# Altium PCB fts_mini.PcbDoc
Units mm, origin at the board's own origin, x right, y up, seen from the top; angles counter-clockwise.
Board outline 46.2 x 15 mm, 2 copper layers (Top Layer, Bottom Layer); 15 components, 14 nets, 42 pads, 0 vias.
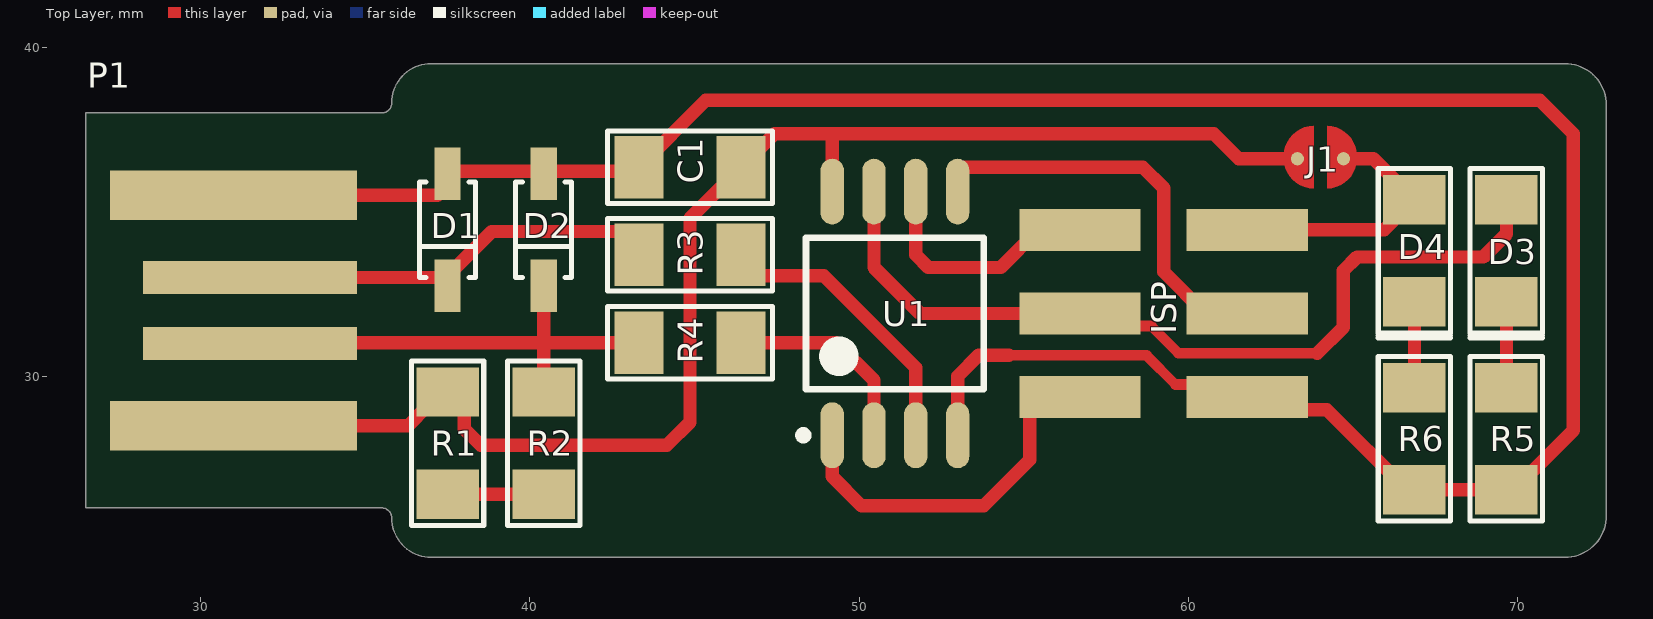
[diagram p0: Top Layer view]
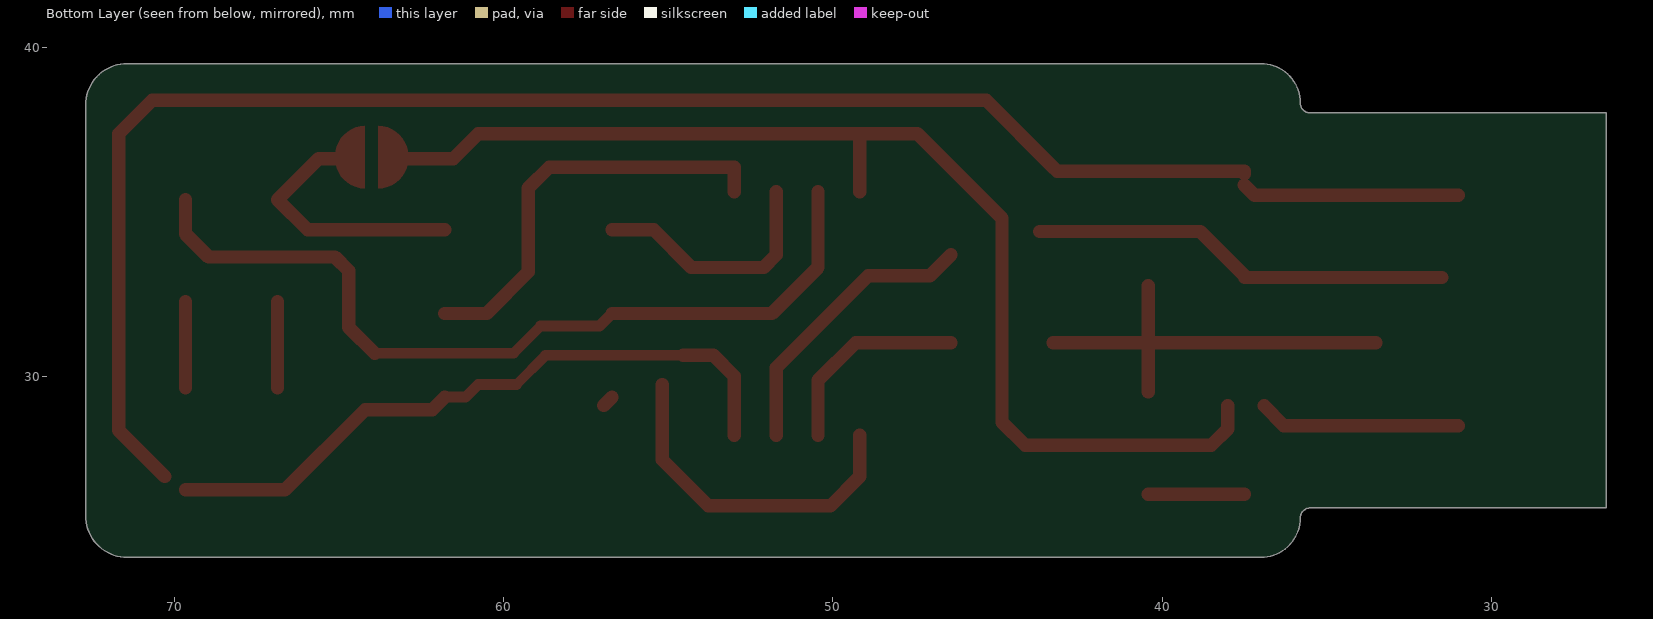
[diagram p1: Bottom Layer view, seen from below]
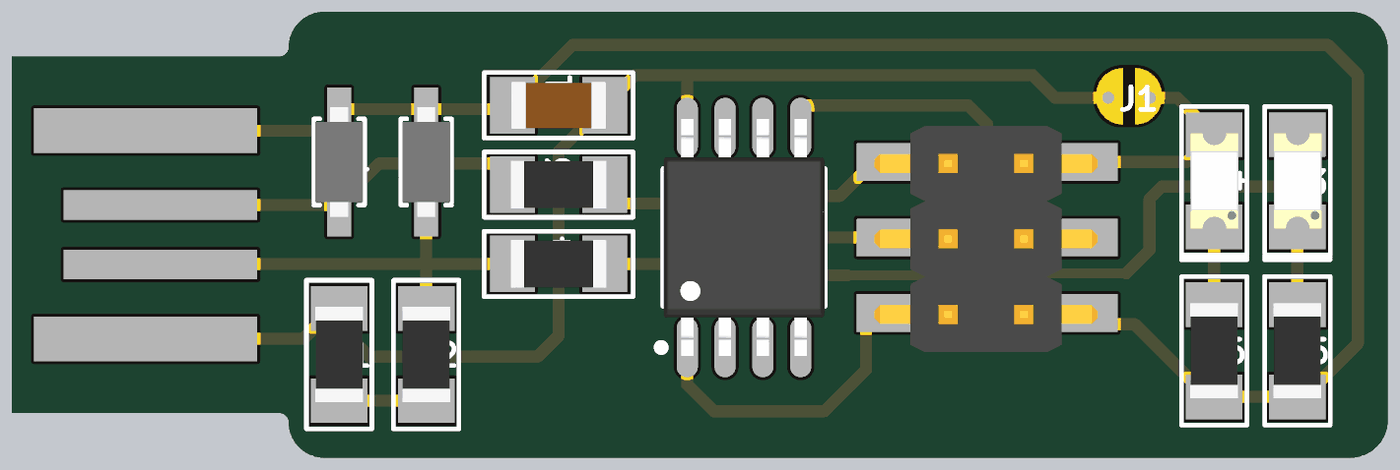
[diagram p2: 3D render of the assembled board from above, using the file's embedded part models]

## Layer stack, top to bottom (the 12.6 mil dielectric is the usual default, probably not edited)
Top Solder: solder mask 0.0102, Solder Resist, Dk 3.5
Top Layer: signal copper 0.0356
Dielectric 1: dielectric 0.32, FR-4, Dk 4.8
Bottom Layer: signal copper 0.0356
Bottom Solder: solder mask 0.0102, Solder Resist, Dk 3.5

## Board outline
26.5,26 26.5,38 35.5,38 ccw(c35.5,38.3) 35.8,38.3 cw(c37,38.3) 37,39.5 71.43,39.5 cw(c71.43,38.23) 72.7,38.23 72.7,25.77 cw(c71.43,25.77) 71.43,24.5 37,24.5 cw(c37,25.7) 35.8,25.7 ccw(c35.5,25.7) 35.5,26

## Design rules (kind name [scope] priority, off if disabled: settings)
Clearance [All] p1: gap=0.406
MinimumSolderMaskSliver [All] p1: minsoldermaskwidth=0
MinimumSolderMaskSliver SilkscreenOverComponentPads [All] p2: minsoldermaskwidth=0.254
PolygonConnect [All] p1: connectstyle=Relief reliefconductorwidth=0.254 reliefentries=4 polygonreliefangle="90 Angle" airgapwidth=0.254
RoutingVias [All] p1: holewidth=0.711 width=1.27 viastyle="Through Hole" minholewidth=0.711 minwidth=1.27 maxholewidth=0.711 maxwidth=1.27
SilkToSilkClearance [All] p1: silktosilkclearance=0
SolderMaskExpansion [All] p1: expansion=0.102
Width [All] p1: maxlimit=2.54 minlimit=0.152 preferedwidth=0.203
28 further rules are at their usual default settings.

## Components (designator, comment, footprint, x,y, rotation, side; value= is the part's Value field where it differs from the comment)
C1 "100nF" 1206C 44.862,36.353 r0 top
D1 "3.3V" SOD123 37.496,34.448 r270 top
D2 "3.3V" SOD123 40.417,34.448 r270 top
D3 "LED GREEN" 1206LED 69.662,33.813 r270 top
D4 "LED RED" 1206LED 66.868,33.813 r270 top
ISP "Header 3X2" 100MIL_SMT_ISP_HEADER 56.708,31.908 r0 top
J1 "Solder Jumper" JMP_1.9mm 64.212,37.607 r180 top
P1 "USB_A" USB_PCB 31,32 r270 top
R1 "1k" 1206R 37.496,27.971 r270 top
R2 "499" 1206R 40.417,27.971 r270 top
R3 "49" 1206R 44.862,33.686 r180 top
R4 "49" 1206R 44.862,31.019 r180 top
R5 "499" 1206R 69.662,28.098 r270 top
R6 "1k" 1206R 66.868,28.098 r270 top
U1 "ATtiny45" SOIC8_WIDE 51.085,31.908 r90 top

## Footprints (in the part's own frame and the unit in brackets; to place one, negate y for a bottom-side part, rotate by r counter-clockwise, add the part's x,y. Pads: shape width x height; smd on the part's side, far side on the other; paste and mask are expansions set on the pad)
100MIL_SMT_ISP_HEADER [mil]
  rect 145x50 smd: 1(0,100) 2(200,100) 3(0,0) 4(200,0) 5(0,-100) 6(200,-100)
  body extent -49,-152 246,148, height 376
1206C [mm] "Chip Capacitor 1206"
  rect 1.5x1.9 smd: 1(-1.55,0) 2(1.55,0)
  silkscreen extent -2.5,-1.1 2.5,1.1, body extent -1.6,-0.8 1.6,0.8, height 1.6
1206LED [mm] "1206 LED"
  rect 1.5x1.9 smd: 1(-1.55,0) 2(1.55,0)
  silkscreen extent -2.5,-1.1 2.65,1.1, body extent -1.6,-0.79 1.6,0.81, height 1.1
1206R [mm] "Chip Resistor, Body 3.2x1.6mm, IPC Low Density"
  rect 1.5x1.9 smd: 1(-1.55,0) 2(1.55,0)
  silkscreen extent -2.5,-1.1 2.5,1.1, body extent -1.6,-0.8 1.6,0.8, height 0.55
JMP_1.9mm [mm]
  round 0.4 smd: 1(-0.5,1) 2(0.9,1)
  Top Layer region: 0,0 0,1.9 0,1.9 -0.344,1.831 -0.636,1.636 -0.831,1.344 -0.9,1 -0.9,1 -0.9,0.9 -0.831,0.556 -0.636,0.264 -0.344,0.069 0,0
  Top Layer region: 0.406,0 0.406,1.9 0.406,1.9 0.751,1.831 1.043,1.636 1.238,1.344 1.306,1 1.306,1 1.306,0.9 1.238,0.556 1.043,0.264 0.751,0.069 0.406,0
SOD123 [mm] "SOD-123; 2 Leads; Body 2.7 x 1.6 mm, (LxW)"
  rect 1.6x0.8 smd: 1(-1.7,0) 2(1.7,0)
  silkscreen extent -1.45,-0.85 1.45,0.85, body extent -1.85,-0.8 1.85,0.8, height 1.15
SOIC8_WIDE [mm] "SOIC, 8-Leads, Body 5.24x5.29mm, Pitch 1.27mm, IPC Low Density"
  oval 2x0.711 smd: 1(-3.7,1.905) 2(-3.7,0.635) 3(-3.7,-0.635) 4(-3.7,-1.905) 5(3.7,-1.905) 6(3.7,-0.635) 7(3.7,0.635) 8(3.7,1.905)
  silkscreen extent -3.82,-2.7 2.3,2.9, body extent -3.99,-2.7 3.99,2.7, height 2.16
USB_PCB [mm]
  rect 1.5x7.5 smd: 1(3.5,0) 4(-3.5,0)
  rect 1x6.5 smd: 2(1,0.5) 3(-1,0.5)

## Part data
C1: library part Capacitor
D1 D2: library part "Zener Diode"
D3 D4: library part LED
ISP: "Header, 3-Pin, Dual row"
R1 R2 R3 R4 R5 R6: library part Resistor

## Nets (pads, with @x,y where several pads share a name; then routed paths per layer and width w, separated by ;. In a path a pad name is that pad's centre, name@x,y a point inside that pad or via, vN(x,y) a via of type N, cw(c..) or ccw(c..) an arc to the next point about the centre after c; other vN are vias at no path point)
GND: C1.1 D1.1 D2.1 ISP.6 P1.4 R5.2 R6.2 U1.4 | length 73.6
  Top Layer w0.305: 58.723,30.638 59.612,29.749
  Top Layer w0.33: 54.549,30.638 58.723,30.638 ; 59.612,29.749 60.772,29.749 61.153,29.368 ISP.6
  Top Layer w0.406: P1.4 37.19,35.5 D1.1@37.5,35.81 ; D1.1 37.496,36.226 43.185,36.226 C1.1 45.344,38.385 70.678,38.385 71.694,37.369 71.694,28.352 R5.2@70.297,26.955 ; U1.4 52.99,30.003 53.625,30.638 54.549,30.638 ; ISP.6 62.169,28.987 64.201,28.987 66.64,26.548 R6.2 R5.2
MISO: ISP.1 U1.6 | length 7.5
  Top Layer w0.406: U1.6 51.72,33.686 52.101,33.305 54.295,33.305 55.438,34.448 ISP.1
MOSI: ISP.4 U1.5 | length 12.9
  Top Layer w0.406: U1.5 52.99,36.353 58.613,36.353 59.248,35.718 59.248,33.178 60.518,31.908 ISP.4
NetD1_2: D1.2 P1.3 R3.2 | length 12.8
  Top Layer w0.406: P1.3 D1.2@37.496,33 ; D1.2@37.496,33.051 38.842,34.397 R3.2@43.719,34.397
NetD2_2: D2.2 P1.2 R2.1 R4.2 | length 13
  Top Layer w0.406: P1.2@33.5,31.019 40.417,31.019 ; R2.1 40.417,31.019 ; D2.2 40.417,31.019 ; R4.2 40.417,31.019
NetD3_2: D3.2 R5.1 | length 2.6
  Top Layer w0.406: R5.1 D3.2
NetD4_2: D4.2 R6.1 | length 2.6
  Top Layer w0.406: R6.1 D4.2
NetR1_2: R1.2 R2.2 | length 2.9
  Top Layer w0.406: R1.2 R2.2
NetR3_1: R3.1 U1.3 | length 8.8
  Top Layer w0.406: R3.1 47.047,33.051 48.926,33.051 51.72,30.257 U1.3
NetR4_1: R4.1 U1.2 | length 6.2
  Top Layer w0.406: R4.1 49.307,31.019 50.45,29.876 U1.2
RST: ISP.5 U1.1 | length 10.8
  Top Layer w0.406: U1.1 49.18,26.955 50.069,26.066 53.787,26.066 55.184,27.463 ISP.5@55.184,29.749 ; ISP.5 ISP.5@56.962,29.114
SCK: D3.1 ISP.3 U1.7 | length 26.1
  Top Layer w0.305: 58.875,31.527 59.701,30.702
  Top Layer w0.33: ISP.3 57.089,31.527 58.875,31.527 ; 59.701,30.702 63.92,30.702
  Top Layer w0.406: U1.7 50.45,33.305 51.847,31.908 ISP.3 ; 63.92,30.702 64.7,31.481 64.7,33.2 65.123,33.623 68.964,33.623 69.662,34.321 D3.1
VCC: C1.2 J1.2 P1.1 R1.1 U1.8 | length 42
  Top Layer w0.406: P1.1 36.3,28.5 R1.1@36.9,29.1 ; R1.1@38,29.1 38,28.4 38.5,27.9 44.156,27.9 44.862,28.606 44.862,34.803 C1.2 47.428,37.369 49.18,37.369 ; U1.8 49.18,37.369 ; J1.2 61.534,36.607 60.772,37.369 49.18,37.369
VPROG: D4.1 ISP.2 J1.1 | length 8.1
  Top Layer w0.406: ISP.2 65.953,34.448 D4.1 65.624,36.607 J1.1

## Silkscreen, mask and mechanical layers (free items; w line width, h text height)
Mechanical 1:
  the board outline again, w0.2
